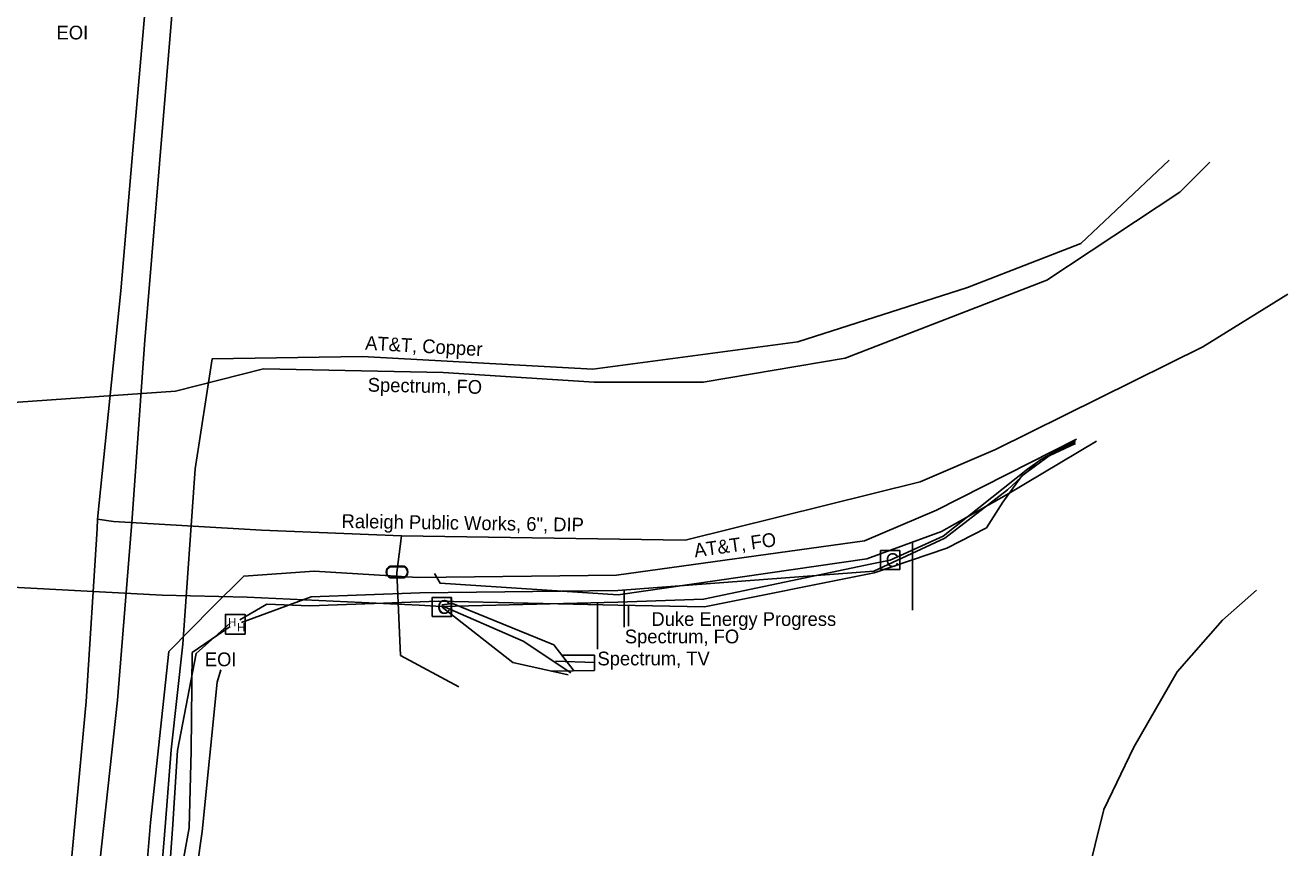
# Model space of a CAD drawing. Extents: x 2070721 to 2083340, y 729290 to 737883.
# Drawn here: x 2082363.4 to 2082731.1, y 736465.9 to 736705.5 of the extents above; entities that cross this region are included whole.
import ezdxf

# ---------------------------------------------------------------- set-up
doc = ezdxf.new("R2010")
doc.units = 0
for name, color, linetype in [('Exist Utilities Gas Valve Text', 7, 'Continuous'), ('Exist Utilities Other Unknown UG SUE LOS B', 7, 'Continuous'), ('Exist Utilities Power UG Cable SUE LOS B', 7, 'Continuous'), ('Exist Utilities Power UG Cable SUE LOS B Leader', 7, 'Continuous'), ('Exist Utilities Power UG Cable SUE LOS B Text', 7, 'Continuous'), ('Exist Utilities Telephone UG Cable SUE LOS C', 7, 'Continuous'), ('Exist Utilities Telephone UG Cable SUE LOS C Text', 7, 'Continuous'), ('Exist Utilities Telephone UG Conduit SUE LOS B', 7, 'Continuous'), ('Exist Utilities Telephone UG FO SUE LOS B', 7, 'Continuous'), ('Exist Utilities Telephone UG FO SUE LOS B Text', 7, 'Continuous'), ('Exist Utilities TV Hand Hole CELL', 7, 'Continuous'), ('Exist Utilities TV Pedestal CELL', 7, 'Continuous'), ('Exist Utilities TV UG Cable SUE LOS C', 7, 'Continuous'), ('Exist Utilities TV UG Cable SUE LOS C Leader', 7, 'Continuous'), ('Exist Utilities TV UG Cable SUE LOS C Text', 7, 'Continuous'), ('Exist Utilities TV UG FO Cable SUE LOS B', 7, 'Continuous'), ('Exist Utilities TV UG FO Cable SUE LOS B Leader', 7, 'Continuous'), ('Exist Utilities TV UG FO Cable SUE LOS B Text', 7, 'Continuous'), ('Exist Utilities TV UG FO Cable SUE LOS C', 7, 'Continuous'), ('Exist Utilities TV UG FO Cable SUE LOS C Text', 7, 'Continuous'), ('Exist Utilities Water Meter CELL', 7, 'Continuous'), ('Exist Utilities Water UG Line SUE LOS B', 7, 'Continuous'), ('Exist Utilities Water UG Line SUE LOS B Text', 7, 'Continuous')]:
    doc.layers.add(name, color=color, linetype=linetype)

msp = doc.modelspace()

# ---------------------------------------------------------------- linework, layer by layer
at = {"layer": 'Exist Utilities Other Unknown UG SUE LOS B'}
msp.add_lwpolyline([(2082395.72, 736292.86), (2082399.83, 736311.96), (2082400.03, 736311.89), (2082404.85, 736370.66), (2082409.06, 736429.49), (2082414.93, 736470.65), (2082419.29, 736514.19), (2082420.3, 736517.77)], dxfattribs=at)
at = {"layer": 'Exist Utilities Power UG Cable SUE LOS B'}
for points in [[(2082482.56, 736545.79), (2082484.21, 736542.97), (2082536.06, 736539.61), (2082608.47, 736550.06), (2082630.23, 736558.05), (2082649.11, 736568.73), (2082675.35, 736584.3)], [(2082633.41, 736326.82), (2082635.39, 736331.76), (2082647.25, 736364.29), (2082654.64, 736387.64), (2082662.17, 736415.15), (2082677.46, 736477.1), (2082686.22, 736495.26), (2082698.83, 736517.21), (2082712.08, 736532.18), (2082721.96, 736540.93)]]:
    msp.add_lwpolyline(points, dxfattribs=at)
at = {"layer": 'Exist Utilities Power UG Cable SUE LOS B Leader'}
msp.add_line((2082621.8, 736554.96), (2082621.8, 736535.09), dxfattribs=at)
at = {"layer": 'Exist Utilities Telephone UG Cable SUE LOS C'}
msp.add_lwpolyline([(2082392.88, 736263.89), (2082382.27, 736265.88), (2082385.19, 736281.09), (2082389.11, 736311.29), (2082396.78, 736370.29), (2082400.63, 736429.15), (2082404.26, 736473.32), (2082405.87, 736494.42), (2082409.26, 736525.23), (2082412.82, 736576.27), (2082417.8, 736608.3), (2082461.47, 736609.04), (2082528.72, 736605.28), (2082588.4, 736613.3), (2082637.77, 736629.11), (2082670.84, 736641.95), (2082696.51, 736666.16)], dxfattribs=at)
at = {"layer": 'Exist Utilities Telephone UG Conduit SUE LOS B'}
for points in [[(2082398.1, 736612.48), (2082411.1, 736769.26), (2082413.2, 736785.84), (2082417.08, 736838.79), (2082421.4, 736882.93), (2082431.06, 736980.24), (2082434.68, 737016.11), (2082441.24, 737055.15)], [(2082369.85, 736250.96), (2082372.63, 736297.63), (2082378.59, 736379.94), (2082382.86, 736441.28), (2082390.24, 736508.9), (2082394.52, 736561.91), (2082398.1, 736612.48)]]:
    msp.add_lwpolyline(points, dxfattribs=at)
at = {"layer": 'Exist Utilities Telephone UG FO SUE LOS B'}
msp.add_lwpolyline([(2082380.42, 736270.25), (2082381.12, 736283.15), (2082384.63, 736311.5), (2082391.98, 736371.16), (2082396.29, 736430.22), (2082399.86, 736473.26), (2082405.23, 736523.1), (2082417.88, 736536.05), (2082427.03, 736545.03), (2082447.47, 736546.52), (2082477.66, 736544.64), (2082535.53, 736545.32), (2082607.76, 736555.33), (2082628.77, 736564.28), (2082669.56, 736584.92)], dxfattribs=at)
at = {"layer": 'Exist Utilities TV Hand Hole CELL'}
msp.add_line((2082424.54, 736531.03), (2082424.54, 736531.03), dxfattribs=at)
msp.add_lwpolyline([(2082421.67, 736528.16), (2082427.42, 736528.16), (2082427.42, 736533.91), (2082421.67, 736533.91), (2082421.67, 736528.16)], dxfattribs=at)
at = {"layer": 'Exist Utilities TV Pedestal CELL'}
for p, q in [((2082615.26, 736549.71), (2082615.26, 736549.71)), ((2082484.65, 736536.03), (2082484.65, 736536.03)), ((2082484.7, 736536.09), (2082484.7, 736536.09))]:
    msp.add_line(p, q, dxfattribs=at)
for points in [[(2082612.49, 736546.94), (2082618.04, 736546.94), (2082618.04, 736552.48), (2082612.49, 736552.48), (2082612.49, 736546.94)], [(2082481.88, 736533.26), (2082487.43, 736533.26), (2082487.43, 736538.81), (2082481.88, 736538.81), (2082481.88, 736533.26)], [(2082481.93, 736533.32), (2082487.48, 736533.32), (2082487.48, 736538.86), (2082481.93, 736538.86), (2082481.93, 736533.32)]]:
    msp.add_lwpolyline(points, dxfattribs=at)
at = {"layer": 'Exist Utilities TV UG Cable SUE LOS C'}
for points in [[(2082346.94, 736593.86), (2082360.72, 736589.21), (2082357.72, 736541.97), (2082403.21, 736539.49), (2082428.03, 736538.87), (2082478.07, 736536.61), (2082484.59, 736536.15), (2082535.98, 736537.5), (2082560.91, 736538.33), (2082609.93, 736548.58), (2082615.28, 736549.68), (2082630.73, 736556.71), (2082655.26, 736576.14), (2082659.68, 736579.26), (2082669.26, 736584.45)], [(2082523.24, 736517.33), (2082517.33, 736525), (2082487.79, 736537.04), (2082484.69, 736536.67)], [(2082484.78, 736536.42), (2082508.4, 736526.14), (2082522.29, 736516.92)], [(2082521.51, 736516.25), (2082505.36, 736519.92), (2082484.78, 736536.03)]]:
    msp.add_lwpolyline(points, dxfattribs=at)
at = {"layer": 'Exist Utilities TV UG Cable SUE LOS C Leader'}
for p, q in [((2082530.08, 736537.27), (2082530.08, 736523.74)), ((2082519.78, 736522.06), (2082529.16, 736522.06))]:
    msp.add_line(p, q, dxfattribs=at)
for points in [[(2082517.8, 736520.25), (2082529.16, 736519.88), (2082529.16, 736522.04)], [(2082516.56, 736517.37), (2082529.16, 736517.56), (2082529.16, 736519.84)]]:
    msp.add_lwpolyline(points, dxfattribs=at)
at = {"layer": 'Exist Utilities TV UG FO Cable SUE LOS B'}
for points in [[(2082425.9, 736532.27), (2082433.71, 736536.84), (2082446.22, 736536.42), (2082483.71, 736537.72), (2082535.95, 736536.62), (2082561.21, 736536.1), (2082610.64, 736546), (2082631.79, 736553.16), (2082643.29, 736559.15), (2082648.05, 736566.62), (2082653.66, 736574.26), (2082661.61, 736580.11), (2082669.14, 736584.07)], [(2082426.4, 736531.55), (2082446.63, 736539.04), (2082478.25, 736540.13), (2082535.97, 736540.82), (2082610.47, 736546.5), (2082631.23, 736556.05), (2082649.4, 736570.19), (2082658.63, 736578.68), (2082669.27, 736583.69)], [(2082383.39, 736263.77), (2082384.87, 736281.05), (2082388.71, 736311.38), (2082396.25, 736370.54), (2082403.33, 736430.4), (2082406.33, 736472.77), (2082407.72, 736494.25), (2082413.13, 736522.51), (2082423.07, 736531.36)], [(2082385.03, 736263.7), (2082391.12, 736281.95), (2082396.82, 736312.11), (2082398.55, 736370.94), (2082403.55, 736430), (2082411.08, 736471.72), (2082411.73, 736494.17), (2082412, 736522.79), (2082423.09, 736530.34)]]:
    msp.add_lwpolyline(points, dxfattribs=at)
at = {"layer": 'Exist Utilities TV UG FO Cable SUE LOS B Leader'}
for p, q in [((2082537.8, 736540.94), (2082537.8, 736530.14)), ((2082539.08, 736536.51), (2082539.08, 736530.49))]:
    msp.add_line(p, q, dxfattribs=at)
at = {"layer": 'Exist Utilities TV UG FO Cable SUE LOS C'}
msp.add_lwpolyline([(2082347.36, 736594.7), (2082407.12, 736598.92), (2082432.73, 736605.4), (2082485.1, 736604.34), (2082529.04, 736601.5), (2082560.83, 736601.5), (2082602.16, 736608.48), (2082660.87, 736631.23), (2082699.66, 736656.83), (2082708.35, 736665.58)], dxfattribs=at)
at = {"layer": 'Exist Utilities Water Meter CELL'}
msp.add_line((2082471.67, 736546.21), (2082471.67, 736546.21), dxfattribs=at)
for points in [[(2082469.63, 736547.91), (2082473.71, 736547.91)], [(2082469.63, 736547.77), (2082473.71, 736547.77)], [(2082473.71, 736544.65), (2082469.61, 736544.65)], [(2082473.71, 736544.51), (2082469.61, 736544.51)]]:
    msp.add_lwpolyline(points, dxfattribs=at)
for centre, radius, start, end in [((2082470.36, 736546.2), 1.86, 113.178, 245.9794), ((2082470.37, 736546.2), 1.73, 115.3009, 243.7824), ((2082472.96, 736546.21), 1.86, 293.6483, 66.3084), ((2082472.97, 736546.21), 1.73, 295.1272, 64.8728)]:
    msp.add_arc(centre, radius, start, end, dxfattribs=at)
at = {"layer": 'Exist Utilities Water UG Line SUE LOS B'}
for points in [[(2082384.35, 736558.86), (2082384.46, 736561.59), (2082391.2, 736628.12), (2082394.55, 736666.82), (2082398.88, 736717.07), (2082400.72, 736736.91)], [(2082472.81, 736556.82), (2082555.61, 736555.54), (2082624.05, 736572.52), (2082645.91, 736581.87), (2082706.38, 736611.81), (2082731.06, 736627.13)], [(2082359.3, 736290.13), (2082359.45, 736292.32), (2082374.67, 736439.46), (2082381.09, 736508.57), (2082384.35, 736558.86)], [(2082384.46, 736561.59), (2082389.12, 736560.96), (2082432.21, 736558.41), (2082472.93, 736556.77)], [(2082472.93, 736556.77), (2082472.27, 736551.43), (2082471.61, 736546.09), (2082472.7, 736521.96), (2082489.65, 736512.8)]]:
    msp.add_lwpolyline(points, dxfattribs=at)

# ---------------------------------------------------------------- texts
at = {"layer": 'Exist Utilities Gas Valve Text'}
msp.add_text('EOI', height=4, dxfattribs=at).set_placement((2082372.49, 736701.33))
at = {"layer": 'Exist Utilities Other Unknown UG SUE LOS B'}
msp.add_text('EOI', height=4, dxfattribs=at).set_placement((2082415.68, 736518.81))
at = {"layer": 'Exist Utilities Power UG Cable SUE LOS B Text'}
msp.add_text('Duke Energy Progress', height=4, dxfattribs=at).set_placement((2082545.74, 736530.54))
at = {"layer": 'Exist Utilities Telephone UG Cable SUE LOS C Text'}
msp.add_text('AT&T, Copper', height=4, rotation=356.7999, dxfattribs=at).set_placement((2082462.29, 736611))
at = {"layer": 'Exist Utilities Telephone UG FO SUE LOS B Text'}
msp.add_text('AT&T, FO', height=4, rotation=7.8901, dxfattribs=at).set_placement((2082558.43, 736550.51))
at = {"layer": 'Exist Utilities TV Hand Hole CELL'}
for p in [(2082422.45, 736530.38), (2082425.03, 736528.92)]:
    msp.add_text('H', height=2.5, dxfattribs=at).set_placement(p)
at = {"layer": 'Exist Utilities TV Pedestal CELL'}
for p in [(2082613.95, 736547.71), (2082483.34, 736534.03), (2082483.39, 736534.09)]:
    msp.add_text('C', height=4, dxfattribs=at).set_placement(p)
at = {"layer": 'Exist Utilities TV UG Cable SUE LOS C Text'}
msp.add_text('Spectrum, TV ', height=4, dxfattribs=at).set_placement((2082530.03, 736519.05))
at = {"layer": 'Exist Utilities TV UG FO Cable SUE LOS B Text'}
msp.add_text('Spectrum, FO ', height=4, dxfattribs=at).set_placement((2082538, 736525.47))
at = {"layer": 'Exist Utilities TV UG FO Cable SUE LOS C Text'}
msp.add_text('Spectrum, FO ', height=4, rotation=358.8396, dxfattribs=at).set_placement((2082463.09, 736598.78))
at = {"layer": 'Exist Utilities Water UG Line SUE LOS B Text'}
msp.add_text('Raleigh Public Works, 6", DIP ', height=4, rotation=359.1143, dxfattribs=at).set_placement((2082455.47, 736559.09))

doc.saveas('drawing.dxf')
